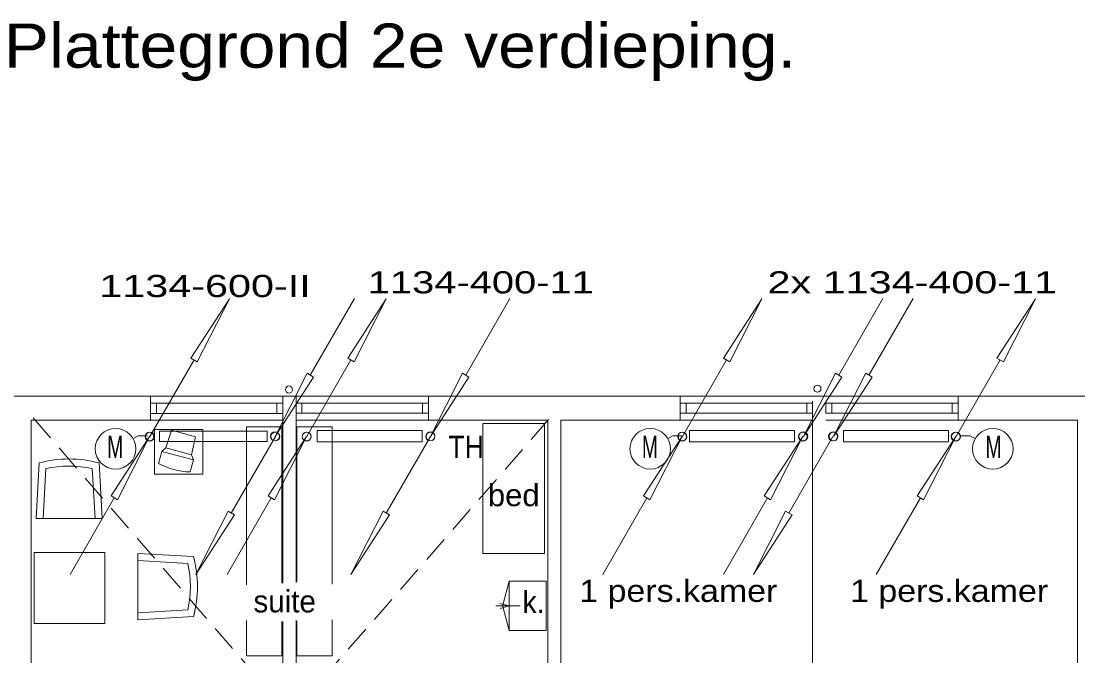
# Model space of a CAD drawing. Extents: x 295824 to 414724, y 24924 to 109024.
# Drawn here: x 301977 to 313944, y 76222 to 83404 of the extents above; entities that cross this region are included whole.
import ezdxf

# ---------------------------------------------------------------- set-up
doc = ezdxf.new("R2010")
doc.units = 0
doc.header["$LTSCALE"] = 100
doc.linetypes.add('MEDIUM_DASHED', pattern=[4.5, 3, -1.5])
doc.layers.add('16', color=7, linetype='Continuous', lineweight=13)
doc.layers.add('61', color=7, linetype='Continuous', lineweight=13)

msp = doc.modelspace()

# ---------------------------------------------------------------- linework, layer by layer
at = {"layer": '16'}
for p, q in [((305751.7, 80264.3), (305251.7, 79398.3)), ((307511.8, 80264.3), (307011.8, 79398.3)), ((311735.8, 80264.3), (311235.8, 79398.3)), ((312077.5, 80264.3), (311577.5, 79398.3)), ((303435.7, 78704.2), (303935.7, 79570.2)), ((305211, 78704.2), (305711, 79570.2)), ((309465.8, 78704.2), (309965.8, 79570.2)), ((312564.3, 78704.2), (313064.3, 79570.2)), ((304856, 78703.1), (304356, 77837.1)), ((306611.4, 78703.1), (306111.4, 77837.1)), ((311170.8, 78703.1), (310670.8, 77837.1)), ((302530.5, 77144.1), (303030.5, 78010.1)), ((304309.5, 77144.1), (304809.5, 78010.1)), ((308562.5, 77144.1), (309062.5, 78010.1)), ((309929.1, 77144.1), (310429.1, 78010.1)), ((311661, 77144.1), (312161, 78010.1))]:
    msp.add_line(p, q, dxfattribs=at)
for points in [[(304335.7, 80263.2), (303971.7, 79549.2), (303899.7, 79591.2)], [(306111, 80263.2), (305747, 79549.2), (305675, 79591.2)], [(310365.8, 80263.2), (310001.8, 79549.2), (309929.8, 79591.2)], [(313464.3, 80263.2), (313100.3, 79549.2), (313028.3, 79591.2)], [(304851.7, 78705.3), (305215.7, 79419.3), (305287.7, 79377.3)], [(306611.8, 78705.3), (306975.8, 79419.3), (307047.8, 79377.3)], [(310835.8, 78705.3), (311199.8, 79419.3), (311271.8, 79377.3)], [(311177.5, 78705.3), (311541.5, 79419.3), (311613.5, 79377.3)], [(303543.4, 78647.6), (304762.8, 78647.6), (304762.8, 78765.4), (303543.4, 78765.4)], [(305327.3, 78644.2), (306517.2, 78644.2), (306517.2, 78773.8), (305327.3, 78773.8)], [(309545, 78644.2), (310734.9, 78644.2), (310734.9, 78773.8), (309545, 78773.8)], [(311288.6, 78644.2), (312478.5, 78644.2), (312478.5, 78773.8), (311288.6, 78773.8)], [(303430.5, 78703.1), (303066.5, 77989.1), (302994.5, 78031.1)], [(305209.5, 78703.1), (304845.5, 77989.1), (304773.5, 78031.1)], [(309462.5, 78703.1), (309098.5, 77989.1), (309026.5, 78031.1)], [(310829.1, 78703.1), (310465.1, 77989.1), (310393.1, 78031.1)], [(312561, 78703.1), (312197, 77989.1), (312125, 78031.1)], [(303956, 77144.1), (304320, 77858.1), (304392, 77816.1)], [(305711.4, 77144.1), (306075.4, 77858.1), (306147.4, 77816.1)], [(310270.8, 77144.1), (310634.8, 77858.1), (310706.8, 77816.1)]]:
    msp.add_lwpolyline(points, close=True, dxfattribs=at)
for points in [[(303406.9, 78710.9), (303300.9, 78710.9), (303241.4, 78676.5)], [(309462.5, 78710.9), (309356.5, 78710.9), (309297, 78676.5)], [(312619.9, 78710.9), (312725.9, 78710.9), (312785.4, 78676.5)]]:
    msp.add_lwpolyline(points, dxfattribs=at)
for centre, radius in [((303045.8, 78565.5), 229.9), ((303430.5, 78702.8), 50), ((303435.7, 78703.9), 50), ((304851.7, 78705.6), 50), ((304856, 78703.4), 50), ((305209.4, 78702.8), 50), ((305211, 78703.9), 50), ((306611.4, 78703.4), 50), ((306611.8, 78705.6), 50), ((309101.4, 78565.5), 229.9), ((309462.5, 78702.8), 50), ((309465.7, 78703.9), 50), ((310829.1, 78702.8), 50), ((310835.8, 78705.6), 50), ((311170.8, 78703.4), 50), ((311177.5, 78705.6), 50), ((312561, 78702.8), 50), ((312564.3, 78703.9), 50), ((312981, 78565.5), 229.9)]:
    msp.add_circle(centre, radius, dxfattribs=at)
at = {"layer": '61'}
for p, q in [((303441.2, 78890.6), (303441.2, 79160.6)), ((304940.1, 79159.3), (304940.1, 77044)), ((305090.1, 79159.3), (305090.1, 77053.9)), ((306589.5, 78890.8), (306589.5, 79160.8)), ((309441.4, 78890.8), (309441.4, 79160.8)), ((312589.8, 78890.8), (312589.8, 79160)), ((303508, 78966.5), (303508, 79080.3)), ((304873, 78965.9), (304873, 79079.9)), ((305156.5, 78966.8), (305156.5, 79080.8)), ((306520.9, 78966.5), (306520.9, 79080.2)), ((309508.3, 78969), (309508.3, 79082.9)), ((310873.3, 78968.4), (310873.3, 79082.4)), ((311156.8, 78969.4), (311156.8, 79083.4)), ((312521.1, 78969.1), (312521.1, 79082.7)), ((302090.1, 78890.8), (304940.1, 78890.8)), ((302090.1, 72179.9), (302090.1, 78890.8)), ((307940.1, 78890.8), (305090.1, 78890.8)), ((307940.1, 72179.6), (307940.1, 78890.8)), ((308090.1, 78890.8), (310940.1, 78890.8)), ((308090.1, 72179.8), (308090.1, 78890.8)), ((313940.1, 78890.8), (311090.1, 78890.8)), ((313940.1, 72179.8), (313940.1, 78890.8)), ((303680.7, 78774.9), (303616.6, 78574.7)), ((303951.1, 78702.4), (303680.7, 78774.9)), ((304529.6, 78815.4), (304929.6, 78815.4)), ((304529.6, 77024.4), (304529.6, 78815.4)), ((304929.6, 78815.4), (304929.6, 77044)), ((305099.7, 78815.4), (305499.7, 78815.4)), ((305099.7, 77063.7), (305099.7, 78815.4)), ((305499.7, 78815.4), (305499.7, 77034.2)), ((303951.1, 78702.4), (303906.4, 78497)), ((303569.9, 78535.4), (303533.7, 78400.5)), ((303616.6, 78574.7), (303569.9, 78535.4)), ((303569.9, 78535.4), (303927.3, 78439.7)), ((302145.9, 77775.2), (302180.8, 78404.6)), ((303891, 78304.4), (303927.3, 78439.7)), ((302226, 77775.2), (302257.4, 78341.2)), ((302782.2, 78341.1), (302815.7, 77775.2)), ((303299, 77380), (303928.4, 77345.1)), ((303299, 77299.9), (303865, 77268.5)), ((307503.4, 77067.3), (307431.1, 76797.3)), ((303864.9, 76743.7), (303299, 76710.2)), ((307629.3, 76787.3), (307353.3, 76787.3)), ((307503.4, 76787.3), (307399.6, 76815.1)), ((307503.4, 76787.3), (307400, 76759.6)), ((307503.4, 76507.3), (307430.4, 76779.9)), ((304529.6, 76223.5), (304529.6, 76621.1)), ((304929.6, 76611.3), (304929.6, 76223.5)), ((304940.1, 76611.3), (304940.1, 75450.1)), ((305090.1, 76626), (305090.1, 75450.1)), ((305099.7, 76223.5), (305099.7, 76616.2)), ((305499.7, 76630.9), (305499.7, 76223.5)), ((304929.6, 76223.5), (304529.6, 76223.5)), ((305499.7, 76223.5), (305099.7, 76223.5))]:
    msp.add_line(p, q, dxfattribs=at)
at = {"layer": '61', "linetype": 'MEDIUM_DASHED'}
for p, q in [((302112.4, 78915.1), (307930.8, 72187.9)), ((307950.5, 78895.5), (302112.4, 72207.6))]:
    msp.add_line(p, q, dxfattribs=at)
at = {"layer": '61'}
for points in [[(301796.6, 66927.7), (301820.1, 79160.8), (332210.1, 79160.8)], [(310940.1, 79104.8), (310940.1, 74040.8), (309025.1, 74040.8), (309025.1, 73890.8), (313005.2, 73890.8)], [(303616.6, 78574.7), (303906.4, 78497), (303927.3, 78439.7)], [(302858.6, 78404.5), (302895.8, 77775.2), (302145.9, 77775.2)], [(303928.3, 76667.3), (303299, 76630.1), (303299, 77380)]]:
    msp.add_lwpolyline(points, dxfattribs=at)
for points in [[(303441.2, 78966.3), (303441.2, 79080.3), (304939.8, 79080.3), (304939.8, 78966.3)], [(305090.2, 78966.5), (305090.2, 79080.5), (306589.6, 79080.5), (306589.6, 78966.5)], [(309441.5, 78968.9), (309441.5, 79082.9), (310940.1, 79082.9), (310940.1, 78968.9)], [(311090.5, 78969.1), (311090.5, 79083.1), (312589.8, 79083.1), (312589.8, 78969.1)], [(304033.8, 78784.9), (303487.6, 78784.9), (303487.6, 78276.9), (304033.8, 78276.9)], [(307203.8, 77382), (307903.8, 77382), (307903.8, 78852), (307203.8, 78852)], [(302123.2, 76589.9), (302923.2, 76589.9), (302923.2, 77389.9), (302123.2, 77389.9)], [(307923.4, 77067.3), (307503.4, 77067.3), (307503.4, 76507.3), (307923.4, 76507.3)]]:
    msp.add_lwpolyline(points, close=True, dxfattribs=at)
for centre in [(305009.5, 79235.9), (310995, 79245.8)]:
    msp.add_circle(centre, 40, dxfattribs=at)
for centre, radius, start, end in [((302519.6, 77164.8), 1285.2, 74.70731, 105.28507), ((303896, 79035.1), 730.8, 240.27982, 269.60839), ((302519.6, 77164.8), 1205.2, 77.41626, 102.56606), ((302688.6, 77006.3), 1285.2, 344.70731, 15.28507), ((302688.6, 77006.3), 1205.2, 347.41626, 12.56606)]:
    msp.add_arc(centre, radius, start, end, dxfattribs=at)

# ---------------------------------------------------------------- texts
at = {"layer": '16'}
for s, width, p in [('1134-400-11', 1.35, (305902.4, 80323.7)), ('2x 1134-400-11', 1.4, (310429.4, 80323.7)), ('1134-600-II', 1.4, (302861.9, 80282.4)), ('M', 0.65, (302951.8, 78462.5)), ('TH', 0.9, (306816, 78462.5)), ('M', 0.65, (309007.3, 78462.5)), ('M', 0.65, (312897.9, 78462.5))]:
    msp.add_text(s, height=250, dxfattribs=dict(at, width=width)).set_placement(p)
at = {"layer": '61'}
for s, height, width, p in [('Plattegrond 2e verdieping.', 500, 1.15, (301778.6, 82877.5)), ('bed', 250, 1.05, (307262.5, 77915.6)), ('1 pers.kamer', 250, 1.15, (308297.5, 76832.7)), ('1 pers.kamer', 250, 1.15, (311364, 76832.7)), ('k.', 250, 0.95, (307655.7, 76705.8))]:
    msp.add_text(s, height=height, dxfattribs=dict(at, width=width)).set_placement(p)
msp.add_text('suite', height=250, dxfattribs=at).set_placement((304608.3, 76713.9))

doc.saveas('drawing.dxf')
